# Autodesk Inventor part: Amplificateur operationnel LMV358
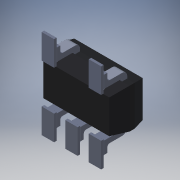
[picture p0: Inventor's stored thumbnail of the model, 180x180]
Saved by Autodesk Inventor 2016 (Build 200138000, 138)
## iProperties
Created: 2018-03
Part Number: Amplificateur operationnel LMV358
Material: Générique
Document SubType Name: Modeling
Designer: Bruno
Density: 1 g/cm^3
Appearance: Par défaut
Author: Bruno
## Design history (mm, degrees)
feature "Composite1"
body "Srf1"
